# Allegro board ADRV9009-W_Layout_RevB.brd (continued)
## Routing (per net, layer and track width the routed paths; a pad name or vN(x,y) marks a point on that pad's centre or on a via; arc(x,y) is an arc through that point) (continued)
VDD1P3_DIG: length 105.7
  TOP w0.203: P904.1 64.36,10.34 R716.1
  TOP w0.254: v1(37.24,35.68) U101.L9 v1(37.24,34.88) U101.L8 v1(37.24,34.08)
  TOP w0.508: v2(70.65,6.97) v2(69.76,6.97) v2(68.87,6.97) v2(67.98,6.97) v2(67.98,6.21) v2(68.87,6.21) v2(69.76,6.21) v2(70.65,6.21) 71.64,5.22 78.97,5.22 80.14,6.39 R923.2
  TOP w1.27: P904.1 68.02,9.57 C951.1
  L5_SIG w0.508: 65.12,8.49 P904.1 ; P904.1 64.04,9.57 ; P904.1 65.12,10.65 ; P904.1 66.2,9.57
  L5_SIG w1.905: 63.57,9.51 62.86,10.22 55.54,10.22 54.11,11.65 54.11,19.71 v2(52.42,21.4) v2(52.42,22.31) v2(53.47,22.31)
  L8_SIG w0.508: 65.12,8.49 P904.1 ; P904.1 66.2,9.57 ; P904.1 65.12,10.65 ; P904.1 64.04,9.57
  L12_PWR w0.635: v1(37.24,34.88) v1(37.24,35.68)
  L12_PWR w1.016: v1(37.24,34.88) v1(37.24,34.08) 38.25,33.07 40.27,33.07
  L12_PWR w1.27: 48.9,27.61 48.9,29.51 46.23,32.18 41.16,32.18 40.27,33.07
  L12_PWR w1.905: 52.66,22.31 v2(52.42,22.31) v2(52.42,21.4) 53.46,21.4 v2(53.47,21.42) v2(53.47,22.31) 52.66,22.31 ; 52.66,22.31 50.17,24.8 50.17,26.34 48.9,27.61
  BOTTOM w0.305: C643.1 37.1,35.54 v1(37.24,35.68) v1(37.24,34.88) 37.24,34.46 ; 37.24,34.46 v1(37.24,34.08) ; 37.24,34.46 C642.1
  BOTTOM w0.508: P904.1 65.12,10.65 ; P904.1 66.2,9.57 ; P904.1 65.12,8.49 ; P904.1 64.04,9.57
  BOTTOM w0.762: C640.1 64.99,9.44 P904.1
VDD_IF_LDO: length 2.9
  TOP w0.254: 58.1,3.62 58.1,2.46 57.63,1.99 U902.5
  TOP w0.305: U902.7 56.66,3.36
VDD_INTERFACE: length 233.6
  TOP w0.203: R102.1 92.59,45.57 94.19,45.57 v2(94.81,44.94) ; C425.1 100.09,39.42 v2(100.09,39.42) ; v2(117.49,47.87) 117.21,48.14 U402.8
  TOP w0.254: U101.M12 v1(38.04,38.08)
  TOP w0.305: U404.4 120.01,22.36 120.51,21.87 120.51,21.54 120.98,21.06 U404.1 122.11,21.06 v2(122.3,20.87) ; v1(137.83,40.26) 137.92,40.34 R833.1 R832.1 ; U403.1 118.84,48.52 118.19,47.87 v2(117.49,47.87) ; R104.1 93.34,36.75 98.32,36.75 100.09,38.52 v2(100.09,39.42) 100.09,39.99 R108.1 ; 51.03,3.61 51.35,3.29 U902.2 ; v2(122.74,53.6) U403.8 ; R106.1 v2(94.81,44.94) ; R718.1 55.25,13.39 v2(56.78,11.86) ; U902.1 51.41,3.94 51.01,4.35 ; R939.2 50.3,3.95
  TOP w0.394: R111.1 132.75,12.32 v1(132.75,12.32) ; P701.1 v2(60.2,66.02)
  TOP w0.508: 46.98,1.55 P907.1 ; P907.1 48.06,2.63 ; P907.1 45.9,2.63 ; P907.1 46.98,3.71
  TOP w0.762: R938.2 131.45,9.75 v2(131.48,9.78)
  L3_PWR w0.508: v2(94.81,44.94) 95.64,45.76 96.52,45.76 97.05,45.23 97.05,44.94 99.47,42.52 99.83,42.52 100.21,42.15 100.21,41.62 100.09,41.5 v2(100.09,39.42)
  L3_PWR w0.635: v2(77.1,18.72) v2(77.86,18.72) 77.87,18.71 v2(78.75,18.71) 80.03,17.42 85.37,17.42 85.83,16.97 93.51,16.97 95.23,15.26 118.91,15.26 119.83,16.17 122.94,16.17 ; 122.94,16.17 122.94,20.23 v2(122.3,20.87) ; 122.94,16.17 124.59,16.17 127.19,13.57 131.5,13.57 v1(132.75,12.32) 132.75,11.05 v2(131.48,9.78)
  L12_PWR w0.203: 56.78,9.95 v2(56.78,11.86)
  L12_PWR w0.508: 45.9,2.63 P907.1 ; P907.1 46.98,3.71 ; P907.1 48.06,2.63 ; P907.1 46.98,1.55 ; 125.36,40.18 125.36,47.16 123.83,48.69 123.83,52.5 v2(122.74,53.6) ; 115.2,40.43 115.2,46.78 116.28,47.87 v2(117.49,47.87)
  L12_PWR w0.762: 78.5,45 78.5,45.89 76.97,47.42 72.65,47.42 71.38,48.69 71.38,52.36 68.2,55.54 66.93,55.54 66.04,56.43 66.04,59.35 64.26,61.13 64.26,61.95 v2(60.2,66.02) ; v1(38.04,38.08) 41.47,38.08 43.63,40.24 45.53,40.24 49.15,43.85 75.2,43.85 76.08,42.97
  BOTTOM w0.305: v1(38.04,38.08) 38.57,38.61 R110.1
  BOTTOM w0.394: v2(121.54,26.84) 123.19,25.19 123.19,22.65 122.3,21.76 v2(122.3,20.87) 122.07,20.63 C421.2 ; v2(122.74,53.6) 122.81,53.53 C423.2 ; P801.J39 v1(132.75,12.32) ; P801.K40 v2(131.48,9.78)
  BOTTOM w0.762: 46.45,3.16 C934.2 ; 46.45,3.16 46.47,3.14 ; 46.45,3.16 46.45,3.14 46.47,3.14 ; 46.47,3.14 P907.1
VDDA1P3_ANLG: length 67.3
  TOP w0.305: R726.1 v2(44.45,16.41)
  TOP w0.394: R916.2 83.03,20.04
  TOP w0.508: P903.1 77.6,15.46 82.18,20.04 83.03,20.04 ; P903.1 65.06,16.54 ; P903.1 65.06,14.38 ; P903.1 63.98,15.46 ; TP601.1 58.8,15.79 ; TP601.1 57.79,14.77 ; TP601.1 59.82,14.77 ; TP601.1 58.8,13.76
  TOP w0.762: C602.1 64.35,16.17 P903.1 65.23,15.29 68.14,15.29 C950.1
  L8_SIG w0.508: 63.98,15.46 P903.1 ; P903.1 66.14,15.46 ; P903.1 65.06,16.54 ; P903.1 65.06,14.38 ; TP601.1 58.8,15.79 ; TP601.1 57.79,14.77 ; TP601.1 59.82,14.77 ; TP601.1 58.8,13.76
  BOTTOM w0.394: R604.1 28.7,14.02 v6(28.71,14.01) ; R605.1 v2(45.85,18.33)
  BOTTOM w0.508: P903.1 66.14,15.46 ; P903.1 65.06,14.38 ; P903.1 65.06,16.54 ; P903.1 63.98,15.46 ; 58.8,13.76 TP601.1 ; TP601.1 59.82,14.77 ; TP601.1 57.79,14.77 ; TP601.1 58.8,15.79 ; v2(7.5,29.5) 7.5,30.39 R607.1 ; R609.1 v2(7.24,19.6) ; v2(41.53,15.15) v2(41.53,15.91) R601.1
  BOTTOM w0.762: 21.59,57.44 v2(21.6,57.44) 21.6,57.44 21.59,57.44 ; 21.59,57.44 20.84,57.44 R610.1 ; 60.07,17.95 59.73,17.6 59.73,16.97 ; 6.99,48.93 R608.1 ; R606.1 22.23,16.49
  BOTTOM w1.016: 8.38,48.93 8.38,48.94 v8(8.32,48.94) ; 8.38,48.93 6.99,48.93 ; 8.38,48.93 v8(9.65,48.93) ; v8(19.64,61.71) 19.59,61.66 19.59,61.66 ; 19.59,61.66 v8(18.69,60.76) ; 19.59,61.66 E602.1
  BOTTOM w1.143: 22.23,16.49 22.25,16.48 22.25,15.62 22.23,15.61 v2(22.23,15.53)
  vias: v2(49.66,18.33) v2(50.33,18.33) v2(61.35,15.03) v2(61.35,14.27) v2(62.24,15.03) v2(62.24,14.27) v2(63.13,15.03) v2(63.13,14.27)
VDDA1P3_AUX_SYNTH: length 32.2
  TOP w0.254: U101.G8 v5(34.04,34.88)
  L12_PWR w0.279: v5(34.04,34.88) 33.64,35.27 33.64,35.8 33.63,35.82 33.63,35.84 33.4,36.07 33.38,36.07 33.36,36.08 33.07,36.08 32.84,36.31 32.84,36.64 32.61,36.87 30.99,36.87 29.85,38.01 29.85,38.9 29.47,39.28 29.4,39.28 29.4,39.28 29.07,39.28 28.84,39.51 28.84,39.79 28.83,39.8 28.83,39.84 28.39,40.28 v6(28.08,40.28)
  L12_PWR w0.508: v6(28.08,40.28) 22.35,53.76 TP612.1
  BOTTOM w0.305: C633.1 28.07,40.29
  BOTTOM w0.508: 27.94,40.87 27.94,40.42 v6(28.08,40.28) ; 27.94,40.87 28,40.81 C633.1 ; 27.94,40.87 C631.1
  BOTTOM w0.762: 20.65,55.18 20.65,54.85 TP612.1 ; 20.65,55.18 20.65,56.12 20.7,56.17 20.7,56.19 ; 20.65,55.18 20.69,56.17 20.7,56.18 20.7,56.19 ; 20.7,56.19 R610.2
VDDA1P3_AUX_VCO_LDO: length 28.3
  TOP w0.254: v5(30.04,35.68) U101.C10
  L12_PWR w0.508: v6(27.19,33.83) 26.81,33.83 25.82,32.84 25.1,32.84 22.53,30.27 v6(19.24,30.27)
  BOTTOM w0.203: 30.06,35.7 v5(30.04,35.68) ; 13.97,30.39 13.98,30.41 C623.1 ; C622.1 29.5,35.7
  BOTTOM w0.394: 30.06,35.7 28.27,35.7 27.64,35.07 27.64,34.28 v6(27.19,33.83)
  BOTTOM w0.508: v6(19.24,30.27) 19.12,30.39 11.33,30.39 ; 8.64,30.9 8.64,30.41 R607.2 8.63,31.97 TP609.1 8.64,30.9 ; 8.64,30.9 9.65,30.9 10.16,30.39 11.33,30.39 ; 11.33,30.39 C621.1
VDDA1P3_BB: length 21.1
  TOP w0.254: v1(31.64,31.68) U101.E5
  BOTTOM w0.203: C604.1 31.5,31.82 v1(31.64,31.68)
  BOTTOM w0.508: v1(31.64,31.68) 31.25,31.29 C605.1 31.38,30.9 31.94,30.33 31.94,29.44 32.7,28.68 32.7,28.25 33.78,27.18 36.36,27.18 37.15,26.39 37.34,26.39 37.46,26.28 37.84,26.28 38.69,25.42 38.69,25.28 39.11,24.86 39.25,24.86 39.81,24.3 39.87,24.3 40.62,23.54 40.62,22.66 TP603.1 41.4,19.76 C603.1 41.4,19.69 41.4,18.06 R601.2
VDDA1P3_CLOCK_SYNTH: length 21.2
  TOP w0.254: v5(34.04,31.68) U101.G5
  L12_PWR w0.394: TP607.1 45.85,22.56 43.86,24.55 42.67,24.55 41,26.23 39.13,26.23 38.83,25.93 37.87,25.93 36.89,26.91 36.89,29.46 36.21,30.14 35.69,30.14 34.15,31.68 v5(34.04,31.68)
  BOTTOM w0.394: R605.2 TP607.1
  BOTTOM w0.508: C617.1 33.98,31.62 v5(34.04,31.68) 33.97,31.74 C616.1
VDDA1P3_CLOCK_VCO_LDO: length 17.2
  TOP w0.254: v1(38.84,28.48) U101.N1
  BOTTOM w0.203: v1(38.84,28.48) 38.67,28.65 C611.1
  BOTTOM w0.508: R603.2 50.04,20.49
  BOTTOM w0.635: C610.1 40.8,27.82 40.25,28.37 C612.1 38.94,28.37 v1(38.84,28.48)
  BOTTOM w1.016: C610.1 42.26,27.82 42.42,27.98 45.21,27.98 47.5,25.69 47.5,24.42 TP605.1 50.04,20.49
VDDA1P3_DES: length 36.5
  TOP w0.254: v1(38.84,35.68) U101.N9 ; v1(39.64,34.88) U101.P9 v1(39.64,35.68)
  BOTTOM w0.203: C638.1 41.02,35.35
  BOTTOM w0.394: v1(38.84,35.68) v1(39.64,35.68) 39.64,35.35 v1(39.64,34.88)
  BOTTOM w0.508: 39.64,35.35 39.71,35.43 39.8,35.35 41.79,35.35 41.87,35.43 48.95,35.43 52.71,31.67 55,31.67 59.73,26.94 59.73,25.23 ; 60.07,21.37 60.07,22.65 59.98,22.73 ; 60.07,19.22 R611.2
  BOTTOM w0.762: 60.07,19.22 TP614.1 60.07,21.37 59.98,21.46 C637.1 59.98,24.97 59.73,25.23
VDDA1P3_RF_LO: length 16.4
  TOP w0.254: v1(30.04,34.08) U101.C8
  L12_PWR w0.635: 28.82,35.46 29.37,34.7 29.99,34.08 v1(30.04,34.08)
  L12_PWR w0.762: 28.82,35.46 25.75,36.46 21.96,38.27 v6(17.27,38.27) v6(17.27,38.98) v6(17.27,39.69)
  BOTTOM w0.508: C627.1 29.97,34.01 v1(30.04,34.08)
VDDA1P3_RF_SYNTH: length 35.5
  TOP w0.254: v5(34.04,34.08) U101.G7
  L12_PWR w0.203: v7(25.53,60.49) v7(25.02,60.49)
  L12_PWR w0.279: v7(25.53,60.49) 25.53,58.46 29.36,54.63 29.36,50.99 28.95,50.58 28.95,45.24 29.09,45.11 29.09,43.98 28.74,43.64 28.74,42.53 29.34,41.93 29.34,40.55 30.36,39.54 31.37,39.54 33.13,37.78 33.78,37.78 33.87,37.68 34.22,37.68 35.26,36.65 35.26,34.75 35.01,34.5 34.46,34.5 v5(34.04,34.08)
  BOTTOM w0.203: v7(25.53,60.49) v7(25.02,60.49)
  BOTTOM w0.508: v5(34.04,34.08) 34.04,34.07 C609.1
VDDA1P3_RF_VCO_LDO: length 31.3
  TOP w0.254: v1(30.04,32.48) U101.C6 ; U101.C5 v3(30.04,31.68)
  L3_PWR w0.508: v1(30.04,32.48) v3(30.04,31.68)
  L12_PWR w0.508: v6(19.18,27.63) 22.01,27.63 v6(25.66,31.29)
  BOTTOM w0.305: 15.13,26.37 15.15,26.36 C628.1 ; 29.09,32.61 C629.1 30.03,32.49 v1(30.04,32.48)
  BOTTOM w0.394: 29.09,32.61 C630.1 27.68,32.61 27.56,32.49 26.86,32.49 v6(25.66,31.29)
  BOTTOM w0.508: v6(19.18,27.63) 16.39,27.63 13.78,25.02 13.78,21.44 12.7,20.36 TP611.1 12.19,19.85 11.09,18.75 10.37,18.75 9.53,19.6 R609.2
VDDA1P3_RX_RF: length 8.4
  TOP w0.254: U101.B1 v1(29.24,28.48)
  L12_PWR w0.394: v6(28.71,23.03) 28.1,23.64 28.1,24.2 28.71,24.81 v7(28.71,26.06)
  BOTTOM w0.305: 29.23,28.47 v1(29.24,28.48) 29.5,28.74 C615.1
  BOTTOM w0.394: v7(28.71,26.06) 28.71,26.71 ; 28.71,26.71 28.71,27.52 28.91,27.71 28.91,28.14 29.23,28.47 ; 28.71,26.71 C613.1 ; v6(28.71,23.03) 28.7,23.03 R612.2
  BOTTOM w0.508: C614.1 28.92,27.73 28.91,27.71
VDDA1P3_RX_TX: length 11.2
  TOP w0.254: v1(30.04,30.88) U101.C3
  BOTTOM w0.394: C618.1 24.25,18.68 24.25,18.67 ; v1(30.04,30.88) 30.04,30.2 30.29,29.95 C620.1
  BOTTOM w0.762: R606.2 23.28,17.7
  BOTTOM w1.143: v6(26.93,25.95) TP608.1 26.4,22.79 24.25,18.67 23.28,17.7
VDDA1P3_SER: length 30.1
  TOP w0.254: v1(39.64,34.08) U101.P8 v1(38.84,34.08) U101.N8
  BOTTOM w0.203: C634.1 40.2,33.81 40.2,33.8
  BOTTOM w0.394: 40.2,32.89 40.2,32.86 C635.1
  BOTTOM w0.508: C635.1 40.28,32.81 ; 40.28,32.81 40.92,32.17 46.23,32.17 48.64,29.76 50.69,29.76 51.36,29.09 53.9,29.09 56.52,26.47 56.52,23.11 56.52,23.1 TP613.1 ; 40.28,32.81 40.2,32.89 40.2,33.8 39.93,34.08 v1(39.64,34.08) v1(38.84,34.08)
  BOTTOM w1.016: E611.2 TP613.1
VDDA1P8_BB: length 67.4
  TOP w0.254: v5(32.44,30.88) U101.E4
  TOP w0.394: R722.1 v2(49.47,17.18)
  L5_SIG w0.114: v2(49.47,17.18) 49.47,16.49 43.69,10.71 41.02,10.71 40.64,11.09 34.67,11.09 33.91,10.33 31.63,10.33 31.37,10.58 29.59,10.58 27.82,8.8 26.55,8.8 TP903.1
  L10_SIG w0.279: 30.94,28.8 31.24,29.1 31.24,30.24 31.49,30.48 32.04,30.48 v5(32.44,30.88)
  L10_SIG w0.305: 30.94,28.8 30.5,28.8
  L10_SIG w0.394: 30.5,28.8 29.83,28.12 29.83,27.62
  L10_SIG w0.508: 25.02,8.04 25.02,15.28 26.86,17.12 26.86,18.52 28.44,20.1 28.44,23.29 27.94,23.79 27.94,25.73 29.83,27.62
  L10_SIG w0.762: TP903.1 25.02,7.28 25.02,8.04
  BOTTOM w0.305: C944.1 32.51,30.95 v5(32.44,30.88) ; 25.61,5.75 R942.2
  BOTTOM w0.508: v5(32.44,30.88) 32.58,30.73 C945.1
  BOTTOM w1.016: C942.1 24.26,8.55 TP903.1 24.35,6.43 ; 25.61,5.75 25.02,5.75 24.35,6.43 ; 24.35,6.43 C943.1
VDDA1P8_TX: length 61.3
  TOP w0.203: U101.E12 v3(31.64,38.08)
  TOP w0.279: C947.1 v4(26.48,41.06)
  TOP w0.305: C948.1 26.3,40.88 v4(26.48,41.06)
  TOP w0.394: v4(47.39,17.17) R724.1
  TOP w0.508: v2(32.17,24.13) 32.18,24.14 C316.1 32.18,25.43 L316.1 ; TP901.1 100.21,4.74 ; TP901.1 99.19,3.72 ; TP901.1 100.21,2.71 ; TP901.1 101.22,3.72 ; L315.2 37.53,25.43 C315.1 37.53,24.14 v2(37.54,24.13) ; v2(37.5,44.02) 37.49,44.01 C308.1 37.49,42.72 L308.1 ; v2(32.13,44.02) 32.15,44.01 C307.1 32.15,42.72 L307.2
  L3_PWR w0.203: 30.68,39.26 30.67,39.25 30.45,39.25 30.45,39.06 30.47,39.04 30.46,39.03 30.46,38.72 30.72,38.46 31,38.46 31.38,38.08 v3(31.64,38.08) 31.64,38.34 31.26,38.72 31.26,39 31,39.26 30.68,39.26
  L3_PWR w0.305: v2(37.5,44.02) 37.21,43.73 32.43,43.73 v2(32.13,44.02)
  L3_PWR w0.394: v4(47.39,17.17) 46.99,16.78 46.99,16.42 ; v2(32.17,24.13) 32.59,24.55 37.12,24.55 v2(37.54,24.13)
  L3_PWR w0.508: TP901.1 101.22,3.72 ; TP901.1 100.21,2.71 ; TP901.1 100.21,4.74 ; TP901.1 99.19,3.72 ; v4(26.48,41.06) 28.64,41.06 30.45,39.25
  L3_PWR w0.762: 34.84,43.73 34.84,46.94 36.32,48.42 36.42,48.42 36.91,48.91 36.91,49.61 36.42,50.1 36.37,50.1 34.62,51.85 34.14,51.85 33.35,52.64 33.35,53.43 31.53,55.25 31.41,55.25 31.37,55.28 ; 38.33,19.51 38.07,19.78 37.67,19.78 34.81,22.64 34.81,24.55
  vias: v2(101.6,4.74) v2(101.6,2.71) v2(101.86,3.72)
VDDA_1P8: length 113.1
  TOP w0.508: 105.48,4.74 P906.1 ; P906.1 106.56,5.82 ; P906.1 107.64,4.74 ; P906.1 106.56,3.66 ; v2(104.9,5.58) v2(104.14,5.58) v2(103.38,5.58) 102.34,6.62 R931.2
  BOTTOM w0.305: 27.05,5.75 R942.1 ; C940.2 105.54,3.72 P906.1 107.7,3.6 C941.2
  BOTTOM w0.508: P906.1 106.56,5.82 ; P906.1 107.64,4.74 ; P906.1 106.56,3.66 ; P906.1 105.48,4.74
  BOTTOM w1.016: 27.05,5.75 27.94,5.75 28.7,6.52 28.7,11.09 30.23,12.61 34.67,12.61 38.48,8.8 39.88,8.8 42.42,6.26 54.23,6.26 58.04,2.45 59.82,2.45 61.09,1.18 102.49,1.18 104.14,2.83
VDDA_3P3: length 141.4
  TOP w0.254: U101.C12 v3(30.04,38.08)
  TOP w0.394: R720.1 v4(51.56,17.18) ; v1(133.42,62.28) R848.1
  TOP w0.508: R927.2 98.73,20.17 99.61,19.29 v2(101.51,19.29) v2(102.27,19.29) v2(103.04,19.29) 103.04,17.69 R935.1
  L3_PWR w0.203: 31,36.89 31.01,36.9 31.02,36.89 31.21,36.89 31.21,37.11 31.22,37.12 31.22,37.43 30.96,37.69 30.67,37.69 30.29,38.08 v3(30.04,38.08) 30.04,37.82 30.42,37.44 30.42,37.16 30.68,36.89 31,36.89
  L3_PWR w0.508: P905.1 104.45,21.42 ; P905.1 102.29,21.42 ; P905.1 103.37,20.34 ; P905.1 103.37,22.5 ; v2(41.53,60.62) 43.44,58.71 45.72,58.71 ; 45.72,58.71 47.75,58.71 49.15,57.32 51.82,57.32 v2(52.2,57.7) ; 45.72,58.71 45.72,59.86 44.33,61.25 v2(44.33,62.14) ; 45.72,58.71 45.72,56.3 ; 31.21,36.89 31.36,36.74 31.88,36.74 32.51,37.38 32.51,38.14 34.04,39.66 35.71,39.66
  L10_SIG w0.203: 59.06,10.71 57.02,12.75 56,12.75 v4(51.56,17.18)
  L12_PWR w0.394: v2(101.51,19.29) v2(102.27,19.29) v2(103.04,19.29) 106.76,19.29 111.28,23.82 114.46,23.82 115.07,24.43 120.53,24.43 122.27,22.69 129.57,22.69 133.84,26.96 134.27,26.96 134.63,27.31 134.63,27.75 136.31,29.43 138.36,29.43 140.99,32.06 140.99,53.25 139.76,54.48 139.76,57.39 134.87,62.28 v1(133.42,62.28)
  BOTTOM w0.305: R120.1 52.39,57.89 v2(52.2,57.7) ; C135.1 v2(44.33,62.14) ; R119.1 v2(41.53,60.62)
  BOTTOM w0.508: 102.29,21.42 P905.1 ; P905.1 103.37,20.34 ; P905.1 103.37,22.5 ; P905.1 104.45,21.42 ; 44.33,61.32 v2(44.33,62.14)
  vias: v2(57.41,8.68) v2(58.43,8.68) v2(58.47,7.41) v2(58.94,8.05) v2(59.45,8.68) v2(59.45,7.41)
1P3_BUCK_OUT: length 25.4
  L8_SIG w0.394: v2(77.64,6.69) v2(76.87,6.69) v2(76.11,6.69) 75.41,7.4 75.41,18.42 77.23,20.24 84.4,20.24 v2(85.18,21.02)
  BOTTOM w0.394: R905.1 85.59,20.61 v2(85.18,21.02)
3P3V_CLK1: length 38.3
  TOP w0.203: U404.6 119.82,20.88 v2(119.82,20.13) ; C440.2 107.12,66.77 v2(107.63,66.77)
  TOP w0.305: C424.2 117.74,55.17 v2(118.11,55.54) 118.53,55.54 118.84,55.23 U403.14
  TOP w0.394: v2(93.44,59.63) 92.84,59.03 C431.2 ; C436.2 90.27,64.8 v2(90.54,65.06) ; C428.2 v2(93.54,54.83) ; C443.2 85.93,62.84 v2(85.14,63.63) ; C438.2 87.38,64.86 87.38,64.9 v2(87.54,65.06) ; C418.1 85.47,60.3 v2(85.14,60.63) ; v2(86.04,65.06) 86.31,64.8 C439.2 ; C426.1 86.11,57.39 v2(86.11,56.73) ; C442.2 85.71,61.57 v2(85.14,62.14) ; C435.2 91.77,64.8 v2(92.04,65.06) ; v2(89.04,65.06) 88.77,64.8 C437.2 ; C433.2 92.97,62.63 v2(93.45,62.63) ; C434.2 93.41,67.17 v2(93.41,66.78) ; C444.2 v2(83.24,65.13) ; v2(83.2,57.05) 83.31,57.16 C441.2 ; C432.2 92.76,60.47 v2(93.42,61.13) ; v2(93.44,58.13) 93.07,57.76 C430.2 ; v2(95.34,56.63) C429.2 ; v2(88.87,56.77) 88.87,57.43 C427.2
  BOTTOM w0.203: 94.24,56.63 U401.72 ; U405.5 v2(107.63,66.77) ; U401.48 v2(90.54,65.06) ; U401.16 86.04,56.73 v2(86.11,56.73) ; 92.04,65.07 U401.51 ; 89.04,55.93 U401.10 ; U401.39 v2(86.04,65.06) ; U401.69 v2(93.44,58.13) ; U401.1 v2(93.54,54.83) ; U401.66 v2(93.44,59.63)
  BOTTOM w0.254: v2(92.04,65.06) 92.04,65.07 ; U401.42 v2(87.54,65.06) ; U401.60 v2(93.45,62.63) ; U401.33 v2(85.14,63.63) ; v2(83.2,57.05) 83.66,57.05 83.72,57.11 83.8,57.11 83.82,57.13 U401.20 ; U401.63 93.42,61.13 93.42,61.13 93.42,61.13 v2(93.42,61.13) ; U401.30 84.98,62.13 85.03,62.08 85.03,62.14 v2(85.14,62.14) ; U401.36 v2(83.24,65.13) ; U401.45 v2(89.04,65.06) ; v2(95.34,56.63) 94.24,56.63 ; v2(88.87,56.77) 88.87,56.85 88.84,56.85 88.84,56.75 89.04,56.54 89.04,55.93 ; v2(93.41,66.78) 93.41,66.91 93.54,66.78 U401.54 ; U401.27 v2(85.14,60.63)
  BOTTOM w0.394: v2(83.2,57.05) 82.98,56.83 R440.1 ; C422.2 v2(119.82,20.13)
  vias: v2(109.99,19.03) v2(109.99,18.27) v2(110.88,19.03) v2(110.88,18.27) v2(111.77,19.03) v2(111.77,18.27)
3P3V_VCXO: length 64.1
  BOTTOM w0.305: 127.01,62.27 127.01,62.26 C938.2
  BOTTOM w0.394: Y401.6 Y402.6 v2(111,63.8) C407.2
  BOTTOM w0.508: E906.2 103.91,25.59 107.97,25.59 109.86,27.48 111.13,27.48 114.18,30.53 116.21,30.53 118.75,33.07 120.53,33.07 126.5,39.04 126.97,39.04 130.06,42.13 130.06,59.74 127.53,62.27 v2(126.23,62.27) v2(125.56,62.27) 125.56,61.43 124.82,60.69 124.35,60.21 R408.1
3P3VAUX: length 104.4
  TOP w0.305: 126.61,19.28 125.11,19.28 ; 126.61,19.28 C703.1 ; 126.61,19.28 127.66,19.28 v2(127.68,19.26) ; 125.11,19.28 C704.1 ; 125.11,19.28 123.44,19.28 U702.8 ; R710.2 v2(113.8,16.05) ; R709.2 v2(113.8,17.83) ; U703.10 v2(45.49,9.59) ; U703.17 U703.16 ; R708.2 113.21,20.73 v2(112.97,20.97)
  TOP w0.635: U703.16 50.55,9.59 51.2,8.94 v8(51.2,7.67)
  L10_SIG w0.394: v2(45.49,9.59) 46.4,8.68 50.18,8.68 v8(51.2,7.67)
  L10_SIG w0.762: v8(51.2,7.67) 52.84,7.67 57.03,3.48 59.19,3.48 61.6,1.06 105.66,1.06 105.96,0.76 107.15,0.76 107.45,1.06 110.12,1.06 113.8,4.75 v2(113.8,16.05) v2(113.8,17.83) 113.8,20.13 v2(112.97,20.97)
  BOTTOM w0.394: C702.1 51.19,7.68 v8(51.2,7.67) 50.91,7.67 50.22,8.37 C701.2 ; P801.D32 v1(139.1,21.21)
ADP5054_VREG: length 20.4
  TOP w0.394: R903.2 87.86,8.29 v2(88.25,8.68) 88.95,9.38 90.64,9.38 91.04,8.98 91.04,8.83 v2(91.07,8.8) 91.4,9.13 91.4,16.32 v2(89.62,18.1)
  BOTTOM w0.203: 89.03,17.5 88.75,17.22 U901.44 ; 89.03,17.5 89.25,17.28 U901.45 ; 89.03,17.5 v2(89.62,18.1) 89.7,18.17 C902.2
  BOTTOM w0.254: v2(91.07,8.8) 90.75,9.12 U901.13 ; U901.18 v2(88.25,8.68)
AUX_SYNTH_VTUNE: length 49.1
  TOP w0.203: J101.1 56.39,35.98 P104.6
  TOP w0.254: v3(39.64,28.48) U101.P1
  L5_SIG w0.114: P104.6 55.12,40.11 55.12,42.08 51.31,45.89 45.85,45.89 45.27,45.31 44.68,45.31 44.42,45.57 37.91,45.57 36.98,44.64 36.98,44.21 36.68,43.91 36.25,43.91 34.74,42.39 34.74,39.28 34.5,39.05 34.5,31.54 34.76,31.28 34.91,31.28 35.17,31.02 35.17,30.78 36.34,29.61 36.58,29.61 37.33,28.86 39.25,28.86 v3(39.64,28.48)
AUXADC_0: length 64.3
  TOP w0.254: U101.F3 v3(32.44,30.08)
  L8_SIG w0.114: v3(32.44,30.08) 32.1,30.41 32.1,32.46 32.77,33.14 32.77,33.32 33.15,33.69 33.33,33.69 33.65,34.01 33.65,34.24 33.9,34.49 34.2,34.49 34.5,34.79 34.5,35.06 34.78,35.34 34.98,35.34 35.3,35.66 35.3,36.62 35.5,36.81 35.78,36.81 36.1,37.14 36.1,37.42 36.3,37.61 38.85,37.61 39.24,38 39.24,38.15 39.44,38.35 39.72,38.35 39.8,38.27 40.98,38.27 43.28,40.56 44.74,40.56 48.92,44.74 68.8,44.74 72.35,48.3 79.19,48.3 79.89,49 79.89,50.97 P103.3
  BOTTOM w0.203: C131.1 81.09,52.3 P103.3
AUXADC_1: length 66.8
  TOP w0.254: U101.F4 v3(32.44,31.68)
  L7_SIG w0.114: v3(32.44,31.68) 32.44,32 32.1,32.34 32.1,33.29 31.65,33.74 31.5,33.74 31.24,33.99 31.24,34.95 30.98,35.21 30.79,35.21 30.48,35.52 30.48,38.2 30.83,38.54 30.98,38.54 31.17,38.74 31.17,38.89 31.63,39.34 31.78,39.34 31.97,39.54 31.97,39.69 32.2,39.92 32.3,40.01 32.72,40.01 32.83,40.13 32.83,41.63 36.32,45.12 37.47,45.12 40.77,48.43 46.74,48.43 47.69,47.47 63.63,47.47 64.65,48.49 79.95,48.49 81.16,49.7
  BOTTOM w0.203: 81.16,49.7 81.09,49.63 C132.1
AUXADC_2: length 84.2
  TOP w0.254: v3(32.44,36.48) U101.F11
  L5_SIG w0.114: P103.5 76.27,54.58 76.24,54.58 75.94,54.88 75.94,54.91 74.55,56.3 66.04,56.3 62.42,59.92 39.69,59.92 38.1,58.33 30.23,58.33 28.58,56.68 27.56,56.68 25.91,55.03 25.91,51.14 26.59,50.46 26.59,49.42 25.08,47.92 25.08,45.89 25.88,45.09 25.88,40.16 29.23,36.81 32.1,36.81 v3(32.44,36.48)
  BOTTOM w0.203: P103.5 78.55,52.3 C133.1
AUXADC_3: length 82.2
  TOP w0.203: U101.E11 v3(31.64,37.28)
  L5_SIG w0.114: 78.62,49.7 77.35,50.97 77.35,52.68 76.08,53.95 66.24,53.95 61.03,59.16 39.94,59.16 38.48,57.69 36.23,57.69 35.72,57.19 29.93,57.19 28.82,56.09 27.73,56.09 26.5,54.86 26.5,51.39 27.18,50.71 27.18,49.03 25.78,47.63 25.78,46.18 26.93,45.03 26.93,42.21 27.08,42.05 28.51,40.62 28.51,40.17 28.83,39.85 28.83,39.61 29.15,39.28 29.31,39.28 29.57,39.02 29.57,38.79 29.96,38.41 30.18,38.41 30.5,38.09 30.5,37.94 30.74,37.7 31.22,37.7 v3(31.64,37.28)
  BOTTOM w0.203: 78.62,49.7 78.55,49.63 C134.1
CLK+: length 7.5
  BOTTOM w0.203: R406.1 92.72,50.77 ; 92.72,50.77 93.54,50.77 C403.2 ; 92.72,50.77 92.28,50.77 92.06,50.99 92.06,51.72 92.97,52.62 92.97,55.06 93.04,55.13 U401.2
CLK-: length 8.1
  BOTTOM w0.203: 92.72,50.42 92.13,50.42 91.7,50.85 91.7,51.86 92.61,52.77 92.61,55.06 92.54,55.13 U401.3 ; 92.72,50.42 93.54,50.42 C405.2 ; 92.72,50.42 R406.2
CLK_RESETB: length 109.9
  TOP w0.203: v2(120.18,22.92) 119.33,22.92 119.1,22.68 119.1,22.04 119.43,21.71 U404.5
  L7_SIG w0.114: v2(120.18,22.92) 120.75,22.35 121.29,22.35 121.3,22.35 130.27,22.35 131,23.09 134.02,23.09 134.83,23.9 134.83,23.94 135.44,24.56 135.49,24.56 135.76,24.83 135.76,24.87 136.81,25.92 136.86,25.92 137.1,26.16 137.1,26.21 137.64,26.75 137.69,26.75 138.87,27.94 138.87,28.55 142.25,31.92 142.25,46.91 141.94,47.22 137.82,47.22 137.68,47.07 134.72,47.07 132.09,49.7 127.39,49.7 125.23,51.86 105.79,51.86 105.28,51.35 93.8,51.35 92.59,52.55 86.97,52.55 86.9,52.62 86.87,52.62 83.45,56.03 v2(83.45,56.36)
  BOTTOM w0.203: v2(83.45,56.36) 83.72,56.63 U401.19
  BOTTOM w0.394: R440.2 82.93,55.84 v2(83.45,56.36)
CLK_SYSREF_REQUEST: length 36.4
  TOP w0.203: U403.13 v2(119.49,56.68)
  L7_SIG w0.114: v2(119.49,56.68) 118.05,56.68 117.67,57.06 109.6,57.06 109.22,56.68 100.46,56.68 97.73,59.41 v2(97.73,65.95)
  BOTTOM w0.254: U401.57 95.53,64.13 96.27,64.87 96.65,64.87 v2(97.73,65.95) ; R441.2 97.73,66.59
  BOTTOM w0.394: 97.73,66.59 v2(97.73,65.95)
DIR_CLK+: length 12.7
  L10_SIG w0.091: v2(95.63,52.09) 95.63,50.79 95.3,50.47 91.34,50.47 90.84,49.96 88.51,49.96 88.42,50.06 88.42,51.18 88.65,51.41 v2(89.35,51.41)
  BOTTOM w0.203: v2(89.35,51.41) 89.35,51.28 89.78,50.85 R416.2 ; v2(95.63,52.09) 94.88,52.09 C402.2
DIR_CLK-: length 12.8
  L10_SIG w0.091: v2(87.12,51.41) 87.89,51.41 88.16,51.14 88.16,49.95 88.4,49.71 90.95,49.71 91.45,50.21 95.36,50.21 95.63,49.95 v2(95.63,49.09)
  BOTTOM w0.203: C404.2 94.87,49.08 94.88,49.09 v2(95.63,49.09) ; v2(87.12,51.41) 87.12,51.16 86.76,50.79 R415.2
EPROM_A0: length 115.9
  TOP w0.203: U703.11 47.52,8.19 v2(46.87,7.54)
  TOP w0.305: v2(119.89,18.21) 118.85,19.25 U702.1 116.61,19.25 115.77,20.09 R711.2 R708.1
  L8_SIG w0.114: v2(46.87,7.54) 48.39,9.06 52.34,9.06 57.67,3.73 83.58,3.73 84.65,4.81 94.18,4.81 102.5,13.13 114.31,13.13 119.39,18.21 v2(119.89,18.21)
  L10_SIG w0.114: v2(119.89,18.21) 124.08,14.02 136.53,14.02 137.37,14.85 137.37,15.05 139.72,17.4 v1(141.64,17.4)
  BOTTOM w0.394: P801.C34 v1(141.64,17.4)
EPROM_A1: length 115.8
  TOP w0.203: U703.13 48.52,7.92 v2(48.14,7.54)
  TOP w0.305: R709.1 R712.2 116.11,18.95 116.46,18.6 U702.2 118.64,18.6 v2(118.85,18.39)
  L8_SIG w0.114: v2(48.14,7.54) 49.14,8.54 52.09,8.54 57.61,3.03 95.7,3.03 97.67,4.99 99.19,4.99 105.8,11.6 114.06,11.6 120.46,18.01 120.46,18.41 120.02,18.84 119.26,18.84 118.85,18.43 v2(118.85,18.39)
  L10_SIG w0.114: v1(140.37,16.13) 137.5,13.25 123.98,13.25 v2(118.85,18.39)
  BOTTOM w0.394: P801.D35 v1(140.37,16.13)
EPROM_A2: length 4.1
  TOP w0.305: R710.1 R713.2 115.63,17.17 115.97,17.51 116.07,17.51 116.5,17.95 U702.3
FMC_CLK_RESETB: length 24.7
  TOP w0.305: v1(140.37,28.83) 138.57,27.03 138.57,24.82 135.57,21.82 129.86,21.82 128.97,22.71 123.77,22.71 122.77,21.71 U404.2
  BOTTOM w0.394: v1(140.37,28.83) P801.D26
FMC_SYSREF_REQUEST: length 46.4
  TOP w0.203: U403.2 v2(119.49,50.59)
  L8_SIG w0.114: v2(119.49,50.59) 121.74,48.33 125.84,48.33 126.86,49.35 129.4,49.35 132.77,45.97 139.13,45.97 141.18,43.92 141.18,43.88 142.25,42.81 142.25,36.37 141.16,35.29 141.16,31.4 141.16,31.4 141.16,30.93 141.16,30.93 141.16,27.08 v1(140.37,26.29)
  BOTTOM w0.394: v1(140.37,26.29) P801.D27
FMCA_SCL: length 107
  TOP w0.203: v2(50.05,7.54) 49.52,8.06 U703.15
  TOP w0.305: U702.6 122.19,17.95 v2(121.8,18.33)
  L8_SIG w0.114: v2(121.8,18.33) 120.91,17.45 120.91,17.19 113.54,9.82 113.54,8.93 107.95,3.34 103.63,3.34 102.24,1.94 95.76,1.94 95.37,2.33 57.41,2.33 53.73,6.02 51.57,6.02 v2(50.05,7.54)
  L10_SIG w0.114: v1(141.64,22.48) 141.06,21.89 133.87,21.89 130.69,18.71 122.68,18.71 122.31,18.33 v2(121.8,18.33)
  BOTTOM w0.394: v1(141.64,22.48) P801.C30
FMCA_SDA: length 110.4
  TOP w0.203: U703.14 v2(49.02,7.54)
  TOP w0.305: U702.5 v2(121.82,17.3)
  L8_SIG w0.114: v2(49.02,7.54) 49.02,6.15 53.6,1.57 95,1.57 95.77,0.8 107.44,0.8 114.68,8.04 114.68,10.07 121.82,17.21 v2(121.82,17.3)
  L10_SIG w0.114: v1(141.64,21.21) 141.64,21.16 137.3,16.81 127.52,16.81 126.88,16.18 125.1,16.18 123.98,17.3 v2(121.82,17.3)
  BOTTOM w0.394: v1(141.64,21.21) P801.C31
FMCA_VADJ: length 13.2
  TOP w0.762: 131.44,6.74 129.45,6.74 TP814.1 ; 131.44,6.74 131.45,6.73 C932.1 ; 131.44,6.74 R938.1
  L12_PWR w0.508: 128.3,6.87 TP814.1 ; TP814.1 127.28,7.89 ; TP814.1 129.31,7.89 ; TP814.1 128.3,8.91
  BOTTOM w0.394: P801.E39 v1(139.1,11.05) ; P801.H40 v1(134.02,11.05) ; P801.G39 v1(136.56,11.05) ; P801.F40 v1(137.83,9.78)
FMCA_VCC_3P3V: length 7.7
  L12_PWR w0.508: 127.36,11.19 TP818.1 ; TP818.1 128.37,10.17 ; TP818.1 129.39,11.19 ; TP818.1 128.37,12.21
  BOTTOM w0.394: P801.D36 v1(140.37,14.86) ; P801.D40 v1(140.37,9.78) ; P801.D38 v1(140.37,12.32) ; P801.C39 v1(141.64,11.05)
FMCA_VCC_12P0V: length 5.9
  TOP w0.508: 121.29,12.87 TP819.1 ; TP819.1 120.28,13.89 ; TP819.1 122.31,13.89 ; TP819.1 121.29,14.91
  BOTTOM w0.394: P801.C35 v1(141.64,16.13) ; P801.C37 v1(141.64,13.59)
FPGA_REF_CLK+: length 49
  TOP w0.203: C803.1 141.01,56.26 140.5,56.77 v1(140.37,56.77)
  L7_SIG w0.091: v2(108.05,65.17) 108.33,64.89 109.45,64.89 110.26,65.7 126.22,65.7 127.36,64.56 132.84,64.56 139.99,57.41 139.99,57.03 140.25,56.77 v1(140.37,56.77)
  BOTTOM w0.203: v2(108.05,65.17) 107.82,64.94 106.43,64.94 102.03,60.53 99.72,60.53 99.59,60.54 99.25,60.88 98.85,60.88 R420.2
FPGA_REF_CLK-: length 49
  TOP w0.203: v1(139.1,56.77) 138.78,56.77 138.5,56.49 C804.1
  L7_SIG w0.091: v2(108.05,64.36) 108.33,64.63 109.55,64.63 110.37,65.44 126.11,65.44 127.26,64.3 132.74,64.3 139.74,57.3 139.74,56.86 139.65,56.77 v1(139.1,56.77)
  BOTTOM w0.203: R419.2 99.25,59.85 99.58,60.18 99.72,60.18 102.17,60.18 106.58,64.58 107.82,64.58 v2(108.05,64.36)
FPGA_SYSREF+: length 44.5
  TOP w0.203: v1(135.29,55.5) 134.86,55.07 134.86,54.66 135.13,54.66 135.13,54.25 134.86,54.25 134.86,53.01 135.06,52.81 R818.1
  L7_SIG w0.091: v2(99.68,63.79) 99.96,63.51 101.12,63.51 103.25,61.38 129.8,61.38 134.81,56.36 134.81,55.73 135.04,55.5 v1(135.29,55.5)
  BOTTOM w0.203: v2(99.68,63.79) 99.45,63.56 99.15,63.56 R424.2
FPGA_SYSREF-: length 44.5
  TOP w0.203: R819.1 135.58,51.79 134.51,52.86 134.51,55.02 v1(134.02,55.5)
  L7_SIG w0.091: v2(99.68,62.98) 99.96,63.26 101.01,63.26 103.15,61.13 129.69,61.13 134.56,56.26 134.56,55.73 134.33,55.5 v1(134.02,55.5)
  BOTTOM w0.203: v2(99.68,62.98) 99.45,63.21 99.16,63.21 R425.2
FPGA_SYSREF_OUT+: length 46.5
  TOP w0.203: v1(139.1,51.69) 139.64,51.15 R834.1
  L7_SIG w0.091: v1(139.1,51.69) 138.6,51.18 136.31,51.18 135,52.49 132.21,52.49 127,57.7 122.3,57.7 121.41,58.59 101.01,58.59 v2(100.74,58.85)
  BOTTOM w0.203: v2(100.74,58.85) 100.48,58.6 100.16,58.6 99.13,57.57 98.27,57.57 98.01,57.82 R451.1
FPGA_SYSREF_OUT-: length 46.5
  TOP w0.203: R835.1 139.13,50.39 v1(139.1,50.42)
  L7_SIG w0.091: v2(100.74,58.09) 100.98,58.33 121.31,58.33 122.2,57.44 126.9,57.44 132.1,52.24 134.9,52.24 136.21,50.93 139.1,50.93 139.29,50.74 139.29,50.61 v1(139.1,50.42)
  BOTTOM w0.203: R452.1 98.01,56.87 98.35,57.22 99.28,57.22 100.31,58.24 100.59,58.24 v2(100.74,58.09)
GP_INTERRUPT: length 113.9
  TOP w0.254: U101.J5 v3(35.64,32.48)
  TOP w0.394: R805.1 129.63,47.21 TP804.1
  L7_SIG w0.114: v3(35.64,32.48) 35.97,32.14 37.38,32.14 37.7,32.46 37.7,32.62 37.9,32.81 38.18,32.81 38.37,32.62 38.37,32.46 38.7,32.14 40.14,32.14 40.14,32.14 44.23,32.14 45.74,30.63 51.98,30.63 52.53,30.08 54.93,30.08 55.15,29.85 77.19,29.85 77.88,30.55 77.88,30.58 78.19,30.88 78.22,30.88 82.34,35.01 82.34,39.26 83.25,40.17 84.2,40.17 84.89,40.85 84.89,42.03 86.9,44.05 100.4,44.05 103.76,40.68 123,40.68 127.72,45.4 TP804.1
GPIO_0: length 116.9
  TOP w0.203: v1(132.75,37.72) 132.78,37.7 R808.1
  TOP w0.254: U101.K8 v3(36.44,34.08)
  TOP w0.305: 98.62,40.18 95.2,40.18 P101.4 ; 98.62,40.18 R108.2 ; 98.62,40.18 98.62,39.67 R109.1
  L7_SIG w0.114: P101.4 95.07,37.64 126.81,37.64 126.95,37.5 129.07,37.5 129.34,37.76 132.71,37.76 v1(132.75,37.72)
  L8_SIG w0.097: 39.76,33.68 39.41,33.68
  L8_SIG w0.114: 39.41,33.68 36.83,33.68 v3(36.44,34.08) ; 39.76,33.68 39.78,33.68 40.17,33.29 43.14,33.29 43.44,33 46.99,33 48.58,34.58 49.98,34.58 50.29,34.27 51.06,34.27 51.56,34.77 59.37,34.77 60.01,35.41 75.57,35.41 77.35,37.19 77.35,39.47 77.85,39.98 83.89,39.98 84.97,41.06 84.97,42.01 85.54,42.58 90.74,42.58 91.38,43.22 94.24,43.22 95.13,42.33 95.13,40.11 P101.4
GPIO_1: length 129.8
  TOP w0.203: R809.1 132.78,36.43 v1(132.75,36.45)
  TOP w0.254: U101.J8 v3(35.64,34.88)
  TOP w0.305: P101.3 93.52,41.73 R107.1 R106.2
  L7_SIG w0.114: P101.3 93.86,40.43 92.78,39.35 92.78,39.33 92.75,39.31 92.75,38.1 94.24,36.61 117.63,36.61 117.64,36.62 130.91,36.62 131.09,36.45 v1(132.75,36.45)
  L8_SIG w0.114: v3(35.64,34.88) 35.35,34.88 34.93,34.46 34.75,34.46 34.37,34.09 34.37,33.94 32.9,32.46 32.9,30.74 33.23,30.41 33.38,30.41 33.57,30.22 33.57,30.06 34.03,29.61 34.18,29.61 34.37,29.42 34.37,29.26 34.7,28.94 36.78,28.94 37.6,28.11 40.14,28.11 42.05,26.2 43.45,26.2 45.04,24.61 54.29,24.61 54.49,24.81 58.56,24.81 59.32,25.57 85.86,25.57 90.56,30.27 90.56,30.78 91.77,31.99 91.77,35.54 92.62,36.39 92.62,40.14 P101.3
GPIO_2: length 124.6
  TOP w0.203: v1(135.29,38.99) 135.79,38.49 R822.1
  TOP w0.254: U101.J7 v3(34.84,33.28)
  TOP w0.305: R105.1 91.51,36.62 R104.2
  TOP w0.394: P101.6 91.46,38.71 R105.1
  L7_SIG w0.114: P101.6 92.59,40.11 92.59,41.76 93.41,42.58 97.92,42.58 102.27,38.24 126.21,38.24 126.5,38.53 129.81,38.53 130.21,38.94 130.66,38.94 131.2,38.4 134.71,38.4 v1(135.29,38.99)
  L8_SIG w0.114: v3(34.84,33.28) 34.25,33.28 33.66,32.68 33.66,31.54 34.78,30.41 34.98,30.41 35.75,29.64 36.71,29.64 37.41,28.94 39.95,28.94 41.41,27.48 46.49,27.48 47.77,26.2 53.6,26.2 54.54,27.14 84.89,27.14 88.04,30.3 88.04,30.8 90.99,33.76 90.99,35.98 91.32,36.31 P101.6
GPIO_3: length 124.5
  TOP w0.203: v1(132.75,35.18) 133.36,35.79 134.18,35.79 134.88,36.49 R823.1 ; R102.2 R103.1
  TOP w0.254: U101.K7 v3(36.44,33.28)
  TOP w0.305: P101.5 91.29,41.41 91.29,43.83 R103.1
  L7_SIG w0.114: P101.5 90.21,40.27 90.21,37.53 92.91,34.83 115.72,34.83 116.16,34.39 118.68,34.39 119.26,34.96 132.54,34.96 v1(132.75,35.18)
  L8_SIG w0.114: v3(36.44,33.28) 35.97,32.81 35.97,32.34 35.78,32.14 35.63,32.14 35.3,31.82 35.3,31.42 36.3,30.41 36.58,30.41 36.9,30.09 36.9,29.94 37.2,29.64 40.01,29.64 41.28,28.37 48.26,28.37 48.77,27.87 52.21,27.87 52.33,27.99 62.33,27.99 62.33,27.98 83.07,27.98 83.37,28.29 83.37,28.55 90.05,35.22 90.05,40.11 P101.5
GPIO_3P3_0: length 61.8
  TOP w0.254: v3(29.35,27.93) 29.49,27.93 U101.C1
  L8_SIG w0.114: v3(29.35,27.93) 29.24,27.93 28.85,28.32 28.85,28.83 28.46,29.23 28.46,31.04 28.81,31.38 28.81,34.92 29.23,35.34 29.38,35.34 29.39,35.35 29.4,35.35 29.7,35.66 29.7,35.82 29.9,36.01 30.09,36.01 31.3,37.22 31.3,37.42 31.5,37.61 31.66,37.61 33.54,39.49 33.54,44.01 34.23,44.7 34.23,47.47 35.56,48.8 35.56,49.47 35.86,49.77 36.24,49.77 38.01,51.55 38.01,51.83 39.31,53.13 46.48,53.13 46.87,53.51 48.52,53.51 48.64,53.38 49.98,53.38 50.36,53.76 65.04,53.76 P102.3
  BOTTOM w0.203: P102.3 C121.1
GPIO_3P3_1: length 54.5
  TOP w0.254: U101.D1 31.2,28.84 v3(31.2,28.31)
  L8_SIG w0.114: v3(31.2,28.31) 30.43,29.09 30.43,34.94 30.83,35.34 30.98,35.34 31.3,35.66 31.3,35.82 32.3,36.81 32.46,36.81 33.7,38.05 33.7,38.15 33.7,38.15 33.7,38.22 33.9,38.41 34.05,38.41 34.5,38.86 34.5,43.19 36.25,44.94 36.52,44.94 37.85,46.27 39.88,46.27 42.17,48.55 59.31,48.55 59.63,48.24 65.09,48.24 P102.4
  BOTTOM w0.203: P102.4 C122.1
GPIO_3P3_2: length 57.6
  TOP w0.254: U101.E1 v3(31.64,29.28)
  L8_SIG w0.114: P102.5 65.29,50.97 67.12,50.97 67.76,50.33 67.76,49.19 66.23,47.66 48.45,47.66 48.2,47.92 45.91,47.92 43.5,45.51 38.26,45.51 36.99,44.23 36.99,44.14 35.3,42.45 35.3,37.24 34.96,36.9 34.71,36.9 34.37,36.57 34.37,36.34 34.18,36.14 34.03,36.14 33.66,35.77 33.66,35.62 33.38,35.34 33.14,35.34 32.9,35.09 32.18,35.09 31.25,34.16 31.25,31.52 31.25,31.52 31.25,29.66 v3(31.64,29.28)
GPIO_3P3_3: length 52.1
  TOP w0.254: U101.C2 v3(30.04,29.28)
  L8_SIG w0.114: v3(30.04,29.28) 29.59,29.72 29.59,34.96 29.97,35.34 30.18,35.34 30.37,35.54 30.5,35.66 30.5,35.82 30.7,36.01 30.89,36.01 32.04,37.16 32.04,37.41 34.05,39.42 34.05,43.73 34.8,44.49 34.8,45.51 36.27,46.97 39.24,46.97 40.91,48.64 40.91,49.84 41.75,50.68 48.93,50.68 49.28,51.03 62.69,51.03 P102.6
GPIO_3P3_4: length 70.6
  TOP w0.254: U101.D2 v3(30.84,29.28)
  L7_SIG w0.114: v3(30.84,29.28) 30.43,29.69 30.43,30.24 30.2,30.46 29.9,30.46 29.59,30.77 29.59,31.8 29.28,32.11 28.77,32.11 27.16,33.72 27.16,35.62 26.23,36.55 26.23,40.55 25.85,40.93 25.85,48.11 26.61,48.87 26.61,55.67 29.66,58.71 39.44,58.71 40.07,59.35 42.46,59.35 48.42,53.38 60.34,53.38 P102.7
  BOTTOM w0.203: P102.7 C123.1
GPIO_3P3_5: length 64.2
  TOP w0.254: U101.E2 v3(31.64,30.08)
  L7_SIG w0.114: v3(31.64,30.08) 32.03,30.46 32.03,31.84 31.8,32.06 31.57,32.06 31.17,32.46 31.17,32.62 30.48,33.31 30.48,34.33 30.27,34.54 29.9,34.54 29.57,34.86 29.57,40.06 29.47,40.17 29.47,42.18 29.85,42.56 29.85,43.97 29.02,44.81 29.02,50.65 29.59,51.22 29.59,53.95 30.31,54.67 34.01,54.67 34.31,54.96 34.73,54.96 34.76,54.94 39.14,54.94 40.26,53.82 41.85,53.82 45.66,50.01 47.18,50.01 48.77,48.43 60.52,48.43 61.48,49.39 P102.8
  BOTTOM w0.203: P102.8 C124.1
GPIO_3P3_6: length 62.4
  TOP w0.254: U101.E3 v3(31.64,30.88)
  L7_SIG w0.114: v3(31.64,30.88) 31.3,31.21 30.81,31.21 30.37,31.64 30.37,31.82 30.18,32.01 29.95,32.01 29.57,32.39 29.57,32.62 29.38,32.81 29.21,32.81 28.77,33.24 28.77,35.34 27.52,36.6 27.52,42.63 26.86,43.28 26.86,45.63 27.82,46.59 27.82,52.11 28.64,52.94 28.64,54.14 29.94,55.44 31.04,55.44 31.23,55.64 34.9,55.64 35.5,56.24 42.17,56.24 45.53,52.87 46.42,52.87 48.34,50.95 57.64,50.95 P102.9
  BOTTOM w0.203: P102.9 C125.1
GPIO_3P3_7: length 38.1
  TOP w0.254: v3(31.64,38.88) U101.E13
  L5_SIG w0.114: v3(31.64,38.88) 31.97,38.54 32.98,38.54 34.1,39.66 34.1,43.28 36.06,45.25 36.06,45.97 36.36,46.27 40.52,46.27 41.59,47.34 45.65,47.34 46.14,47.83 47.22,47.83 47.71,47.34 57.84,47.34 58.94,48.43 P102.10
  BOTTOM w0.203: P102.10 C126.1
GPIO_3P3_8: length 55.1
  TOP w0.254: v3(30.84,38.88) U101.D13
  L5_SIG w0.114: v3(30.84,38.88) 31.21,39.25 33.02,39.25 33.53,39.76 33.53,44 33.74,44.21 33.74,44.57 36.13,46.97 40.01,46.97 41.47,48.43 57.1,48.43 57.66,49 57.66,50.98 P102.11
  L10_SIG w0.114: P102.11 54.88,53.76 52.83,53.76 47.69,58.9 v2(47.69,61.32)
  BOTTOM w0.203: U102.1 v2(47.69,61.32) ; P102.11 C127.1
GPIO_3P3_9: length 55.5
  TOP w0.203: P102.12 56.26,49.57 C128.1
  TOP w0.254: v3(30.04,38.88) U101.C13
  L5_SIG w0.114: P102.12 55.18,50.92 55.18,53.19 53.41,54.97 48.96,54.97 46.33,57.6 v2(42.01,57.6) 41.83,57.6 40.28,56.05 35.37,56.05 34.86,55.54 30.16,55.54 28.57,53.94 28.57,52.29 28.2,51.92 28.2,45.63 28.97,44.85 28.97,43.13 28.83,42.99 28.83,42.56 28.97,42.42 28.97,40.42 29.37,40.01 29.38,40.01 29.57,39.82 29.57,39.81 30.04,39.35 v3(30.04,38.88)
  BOTTOM w0.203: v2(42.01,57.6) 43.18,58.78 44.33,58.78
GPIO_3P3_10: length 46.4
  TOP w0.254: U101.D14 v3(30.84,39.68)
  L5_SIG w0.114: P102.13 52.47,53.63 49.61,53.63 49.36,53.38 48.93,53.38 48.36,53.95 47.56,53.95 44.9,56.62 v2(44.33,56.62) 41.59,56.62 39.75,54.78 34.92,54.78 34.73,54.96 34.31,54.96 34.12,54.78 30.39,54.78 29.41,53.8 29.41,50.82 28.89,50.3 28.89,45.82 29.41,45.31 29.41,44.9 29.53,44.78 29.53,43.32 29.85,42.99 29.85,42.56 29.47,42.17 29.47,40.63 30.42,39.68 v3(30.84,39.68)
  BOTTOM w0.203: v2(44.33,56.62) 44.33,57.51 ; P102.13 C129.1
GPIO_3P3_11: length 45.7
  TOP w0.203: P102.14 53.85,49.7 C130.1
  TOP w0.254: U101.E14 v3(31.64,39.68)
  L5_SIG w0.114: v3(31.64,39.68) 31.96,39.68 32.3,40.01 32.43,40.01 32.7,40.28 32.7,46.2 35.56,49.06 35.56,49.47 36.29,50.2 36.71,50.2 37.59,51.09 37.59,51.47 39.37,53.25 41.53,53.25 43.88,55.6 v2(44.83,55.6) 45.09,55.6 47.06,53.63 47.06,52.81 48.45,51.41 50.1,51.41 50.61,50.9 52.66,50.9 P102.14
  BOTTOM w0.203: U102.2 48.01,60.05 46.99,59.03 46.99,57.25 45.34,55.6 v2(44.83,55.6)
GPIO_4: length 113.1
  TOP w0.203: P101.8 88.78,37.02 88.78,37.01 R707.2 ; R812.1 132.78,30.08 v1(132.75,30.1)
  TOP w0.254: U101.K6 v3(36.44,32.48)
  L7_SIG w0.114: v1(132.75,30.1) 130.1,32.75 118.31,32.75 117.69,33.37 113.72,33.37 113.42,33.07 92.32,33.07 88.78,36.61 P101.8
  L8_SIG w0.114: P101.8 88.78,36.09 88.15,35.46 87.62,35.46 83.72,31.56 62.93,31.56 61.22,29.85 55.55,29.85 55.44,29.96 54.18,29.96 53.48,29.26 49.67,29.26 49.36,28.95 41.47,28.95 39.87,30.54 38.98,30.54 37.1,30.54 36.9,30.74 36.9,30.89 36.58,31.21 36.41,31.21 36.2,31.42 36.21,31.43 36.1,31.54 36.1,31.82 36.21,31.92 36.21,31.93 36.44,32.16 v3(36.44,32.48)
GPIO_5: length 63.2
  TOP w0.203: R705.2 89.91,43.67 R813.1
  TOP w0.254: U101.K5 v3(36.44,31.68)
  TOP w0.305: P101.7 88.82,41.42 R705.2
  L8_SIG w0.097: 39.89,31.29 39.51,31.29
  L8_SIG w0.114: 39.89,31.29 40.78,30.4 49.67,30.4 49.92,30.65 53.6,30.65 54.3,31.35 59.88,31.35 61.42,32.88 82.25,32.88 84.46,35.1 85.54,35.1 87.51,37.06 87.51,40.11 P101.7 ; v3(36.44,31.68) 36.76,31.68 37.15,31.29 39.51,31.29
GPIO_6: length 120
  TOP w0.203: R843.1 141.67,33.93 v1(141.65,33.95)
  TOP w0.254: U101.L5 v3(37.24,31.68)
  TOP w0.305: P101.10 86.65,38.44 R706.2
  L7_SIG w0.114: v1(141.65,33.95) 141.11,34.49 141.11,35.06 137.03,39.14 137.03,39.18 135.27,40.93 125.03,40.93 124.03,39.93 123.27,39.93 123.22,39.98 102.94,39.98 99.63,43.28 88.97,43.28 87.51,41.82 87.51,40.11 P101.10
  L8_SIG w0.114: P101.10 86.24,37.77 84.97,36.5 82.81,36.5 82.81,36.49 82.65,36.49 80.16,34.01 80.16,33.89 79.66,33.39 60.4,33.39 59.77,32.75 57.85,32.75 56.96,31.86 55.32,31.86 55.19,31.98 49.85,31.98 49.28,31.42 40.52,31.42 39.89,32.05 37.61,32.05 v3(37.24,31.68)
GPIO_7: length 123.4
  TOP w0.203: v3(137.8,31.35) 138.69,31.35 139.26,31.92 R844.1
  TOP w0.254: U101.L6 v3(37.24,32.48)
  TOP w0.305: R702.2 86.23,43.62 86.23,41.4 P101.9
  L7_SIG w0.114: P101.9 86.24,40.81 84.97,39.54 84.97,37.52 89.54,32.94 89.54,32.3 90.43,31.42 91.07,31.42 91.2,31.28 113.6,31.28 114.49,30.39 117.79,30.39 118.93,29.26 120.72,29.26 121.1,29.64 126.17,29.64 126.88,28.93 130.64,28.93 130.7,28.99 131.31,28.99 132.07,28.23 134.49,28.23 135.65,29.38 136.66,29.38 137.16,29.88 137.16,30.71 v3(137.8,31.35)
  L8_SIG w0.114: P101.9 86.24,40.43 84.97,39.16 84.97,38.27 84.34,37.64 81.03,37.64 78.11,34.72 60.72,34.72 59.38,33.38 49.6,33.38 48.2,31.98 47.25,31.98 47.18,32.05 40.65,32.05 39.76,32.94 38.7,32.94 37.7,32.94 v3(37.24,32.48)
GPIO_8: length 131.5
  TOP w0.203: R827.1 136.18,29.72 v1(136.56,30.1)
  TOP w0.254: U101.L12 v3(37.24,38.08)
  L5_SIG w0.091: v1(136.56,30.1) 136.56,30.8 136.47,30.89 135.86,30.89 135.77,30.8 135.77,29.75 135.96,29.56 138.5,29.56 138.81,29.87 138.81,37.55 136.81,39.54 131.22,39.54 129.95,40.81 124.11,40.81 123.86,41.07 103.13,41.07 101.55,42.65 92.99,42.65 92.41,43.23 85.16,43.23 84.52,42.59 84.52,42.2 84.84,41.89 84.84,40.62 83.7,39.48 P101.12
  L10_SIG w0.091: P101.12 83.7,37.64 82.73,36.67 73.44,36.67 67.41,42.7 56.27,42.7 55.56,43.41 48.83,43.41 48.14,42.71 43.37,42.71 42.74,42.08 38.08,42.08 37.05,41.04 37.05,40.06 37.1,40 37.37,40 37.56,39.81 37.56,38.47 37.42,38.33 37.42,38.26 v3(37.24,38.08)
GPIO_9: length 123
  TOP w0.203: R810.1 134.33,33.6 v1(134.02,33.91)
  TOP w0.254: U101.K12 v3(36.44,38.08)
  L5_SIG w0.091: P101.11 82.55,40.24 82.55,38.44 83.25,37.75 84.16,37.75 84.17,37.76 84.22,37.76 84.89,38.42 84.89,39.41 85.72,40.24 101.58,40.24 102.15,39.66 124.06,39.66 129.27,34.46 131.38,34.46 132.44,33.4 133.93,33.4 134.02,33.49 v1(134.02,33.91)
  L10_SIG w0.091: v3(36.44,38.08) 36.08,38.43 36.08,39.08 35.85,39.31 35.76,39.31 35.66,39.4 35.66,42.39 36.49,43.22 39.35,43.22 40.52,44.39 73.91,44.39 75.72,42.58 79.21,42.58 79.76,42.03 79.76,38.03 80.48,37.31 81.77,37.31 82.55,38.1 82.55,40.24 P101.11
GPIO_10: length 123
  TOP w0.203: R811.1 134.33,32.33 v1(134.02,32.64)
  TOP w0.254: U101.J12 v3(35.64,38.08)
  L5_SIG w0.091: v1(134.02,32.64) 134.02,33.06 133.93,33.15 132.33,33.15 131.28,34.2 129.16,34.2 123.95,39.41 102.05,39.41 101.48,39.98 85.82,39.98 85.14,39.3 85.14,38.32 84.33,37.5 84.28,37.5 84.26,37.49 83.14,37.49 82.3,38.33 82.3,39.89 82.21,39.98 81.25,39.98 81.16,39.89 P101.14
  L10_SIG w0.091: P101.14 81.16,39.16 81.71,39.71 82.21,39.71 82.3,39.62 82.3,38.2 81.66,37.57 80.58,37.57 80.01,38.14 80.01,42.14 79.31,42.84 75.82,42.84 74.01,44.65 40.42,44.65 39.24,43.47 36.39,43.47 35.41,42.5 35.41,39.17 35.31,39.07 35.31,38.4 v3(35.64,38.08)
GPIO_11: length 117.2
  TOP w0.203: R824.1 135.26,35.14 v1(135.29,35.18)
  TOP w0.254: U101.H12 v3(34.84,38.08)
  L5_SIG w0.091: P101.13 80.72,41.39 80.01,40.68 80.01,38.2 81.28,36.93 87.21,36.93 87.74,37.47 115.59,37.47 116.44,36.62 117.92,36.62 118.3,37 122.62,37 126.94,32.68 128.27,32.68 128.56,32.97 130.01,32.97 130.8,32.19 134.21,32.19 134.48,32.45 134.48,32.82 135.1,33.44 135.46,33.44 135.8,33.78 135.8,35.09 135.71,35.18 v1(135.29,35.18)
  L7_SIG w0.091: P101.13 80.52,40.74 80.27,40.74 80.04,40.97 80.04,42.12 79.01,43.16 65.62,43.16 62.74,40.28 45.85,40.28 44.02,38.45 35.21,38.45 35.07,38.31 v3(34.84,38.08)
GPIO_12: length 116.8
  TOP w0.203: v1(136.56,35.18) 136.53,35.14 R825.1
  TOP w0.254: U101.H11 v3(34.84,37.28)
  L5_SIG w0.091: P101.16 79.45,38.85 79.76,38.53 79.76,38.1 81.18,36.68 87.31,36.68 87.85,37.21 115.48,37.21 116.33,36.36 118.03,36.36 118.41,36.74 122.52,36.74 126.83,32.42 128.38,32.42 128.67,32.72 129.91,32.72 130.69,31.93 134.32,31.93 134.73,32.35 134.73,32.71 135.2,33.19 135.57,33.19 136.06,33.67 136.06,35.09 136.15,35.18 v1(136.56,35.18)
  L7_SIG w0.091: v3(34.84,37.28) 35.25,37.69 39.71,37.69 39.92,37.89 39.92,38.06 40.06,38.2 44.13,38.2 45.96,40.02 62.85,40.02 65.72,42.9 78.9,42.9 79.79,42.02 79.79,40.9 78.62,39.73 P101.16
GPIO_13: length 121.4
  TOP w0.203: R831.1 135.32,42.77 v1(135.29,42.8)
  TOP w0.254: U101.J11 v3(35.64,37.28)
  L5_SIG w0.091: v1(135.29,42.8) 135.39,42.9 135.39,43.53 135.75,43.88 135.75,44.26 135.38,44.62 132.5,44.62 131.62,43.73 125.22,43.73 124.71,44.24 116.59,44.24 114.69,42.34 104.66,42.34 102.93,44.06 92.82,44.06 92.14,44.74 78.47,44.74 76.88,43.16 76.31,43.16 75.64,42.49 75.63,42.49 74.98,41.84 74.98,40.61 75.3,40.29 77.52,40.29 P101.15
  L7_SIG w0.091: v3(35.64,37.28) 36.07,36.84 36.54,36.84 36.7,36.69 36.83,36.69 36.91,36.61 36.91,36.34 37.1,36.15 37.34,36.15 37.71,35.78 37.71,35.54 37.9,35.35 38.14,35.35 38.77,34.72 39.26,34.72 39.48,34.5 39.79,34.5 39.99,34.7 42.02,34.7 42.55,35.23 48.97,35.23 49.19,35.45 51.74,35.45 52.28,34.9 73.2,34.9 75.42,37.12 76.33,37.12 77.47,38.26 77.47,40.24 P101.15
GPIO_14: length 121.4
  TOP w0.203: v1(136.56,42.8) 136.46,42.7 R830.1
  TOP w0.254: U101.K11 v3(36.44,37.28)
  L5_SIG w0.091: P101.18 77.16,38.85 77.35,39.03 77.35,39.79 77.1,40.03 75.2,40.03 74.73,40.5 74.73,41.95 75.52,42.74 75.53,42.74 76.2,43.41 76.77,43.41 78.36,45 92.25,45 92.93,44.32 103.04,44.32 104.76,42.59 114.58,42.59 116.49,44.5 124.81,44.5 125.32,43.99 131.52,43.99 132.4,44.87 135.49,44.87 136,44.36 136,43.78 135.64,43.42 135.64,43.09 135.93,42.8 v1(136.56,42.8)
  L7_SIG w0.091: P101.18 76.57,39.33 77.12,39.33 77.22,39.23 77.22,38.37 76.23,37.38 75.31,37.38 73.09,35.16 52.39,35.16 51.84,35.7 49.09,35.7 48.86,35.48 42.45,35.48 41.92,34.95 40.1,34.95 39.79,35.25 39.48,35.25 39.2,34.97 38.88,34.97 38.36,35.49 38.36,35.81 38.17,36 37.85,36 37.56,36.29 37.56,36.61 37.37,36.8 37.08,36.8 36.94,36.94 36.8,36.94 36.47,37.28 v3(36.44,37.28)
GPIO_15: length 131.8
  TOP w0.203: R826.1 135.62,30.42 v1(135.29,30.1)
  TOP w0.254: U101.L11 v3(37.24,37.28)
  L5_SIG w0.091: P101.17 77.28,42.58 84.15,42.58 85.05,43.48 92.51,43.48 93.09,42.9 101.66,42.9 103.24,41.32 123.96,41.32 124.22,41.07 130.06,41.07 131.33,39.8 136.91,39.8 139.06,37.65 139.06,29.76 138.6,29.3 135.86,29.3 135.29,29.87 v1(135.29,30.1)
  L10_SIG w0.091: P101.17 75.64,41.83 75.05,41.83 74.81,41.59 74.81,37.08 74.71,36.99 73.48,36.99 67.51,42.96 56.38,42.96 55.67,43.66 48.73,43.66 48.03,42.97 43.27,42.97 42.63,42.33 37.98,42.33 36.79,41.15 36.79,37.37 36.88,37.28 v3(37.24,37.28)
GPIO_16: length 115.5
  TOP w0.203: v1(141.64,49.15) 141.64,48.84 R817.1
  TOP w0.254: U101.M11 v3(38.04,37.28)
  L5_SIG w0.091: v3(69.67,41.88) 70.04,41.88 73.54,45.38 74.19,45.38 77.37,48.55 87.12,48.55 88.9,50.33 97.16,50.33 102.24,55.41 109.2,55.41 109.84,54.78 123.23,54.78 125.39,52.62 130.18,52.62 132.84,49.95 140.85,49.95 141.1,49.7 141.1,49.32 141.27,49.15 v1(141.64,49.15)
  L7_SIG w0.091: v3(69.67,41.88) 69.67,41.51 65.85,37.7 52.03,37.7 51.59,37.25 48.22,37.25 48.03,37.06 41.09,37.06 40.83,36.8 38.82,36.8 38.35,37.28 v3(38.04,37.28)
GPIO_17: length 115.4
  TOP w0.203: v1(140.37,49.15) 140.37,48.84 R816.1
  TOP w0.254: U101.M10 v3(38.04,36.48)
  L5_SIG w0.091: v3(70.22,41.33) 70.22,41.7 71.15,42.64 73.64,45.12 74.3,45.12 77.47,48.3 87.23,48.3 89.01,50.08 97.26,50.08 102.34,55.16 109.1,55.16 109.73,54.52 123.13,54.52 125.29,52.36 130.07,52.36 132.74,49.7 140.74,49.7 140.85,49.59 140.85,49.38 140.61,49.15 v1(140.37,49.15)
  L7_SIG w0.091: v3(38.04,36.48) 38.38,36.48 38.77,36.09 38.91,36.09 39.16,36.34 39.22,36.34 39.47,36.09 39.75,36.09 39.94,36.28 39.94,36.46 40.02,36.55 40.93,36.55 41.19,36.81 48.14,36.81 48.33,37 51.69,37 52.14,37.44 65.96,37.44 69.85,41.33 v3(70.22,41.33)
GPIO_18: length 34.6
  TOP w0.203: R113.1 58.99,36.42 58.99,35.29 R704.2
  TOP w0.254: U101.J3 v3(34.84,30.88)
  TOP w0.305: R113.1 58.99,38.77 P104.4
  L8_SIG w0.114: v3(34.84,30.88) 34.5,31.21 34.5,31.82 34.83,32.14 34.98,32.14 35.19,32.35 35.19,33.32 36.36,34.49 41.75,34.49 42.67,35.41 48.39,35.41 49.91,36.93 52.07,36.93 52.71,37.57 57.66,37.57 P104.4
  BOTTOM w0.203: R837.1 P104.4
INPUT_VOLTAGE: length 42
  TOP w0.203: DS901.A 121.36,5.44 CR901.C
  TOP w0.305: R714.2 v2(55.9,7.29)
  L7_SIG w0.114: v2(55.9,7.29) 56.41,6.78 60.21,6.78 62.37,4.62 80.18,4.62 v2(84.09,8.52)
  BOTTOM w0.254: 85.26,17.59 85.75,17.1 U901.38 ; U901.36 84.03,15.92 83.53,16.42 ; v2(92.49,13.17) 92.8,13.17 v2(93.15,12.81) ; v2(92.49,13.17) 92.24,13.42 U901.6 ; v2(92.49,13.17) 92.24,12.92 U901.7 ; U901.22 86.25,9.16 v2(85.59,8.5)
  BOTTOM w0.394: R909.1 v2(92.94,18.39)
  vias: v2(83.38,18.28) v2(83.71,16.73) v2(84.24,18.28) v2(84.57,16.73) v2(84.82,8.5) v2(98.77,13.32) v2(98.77,12.43) v2(98.77,11.57) v8(117.74,6.02) v8(117.74,4.3) v8(119.26,6.02) v8(119.26,4.3) v8(123.71,6.02) v8(123.71,4.3) v8(125.23,6.02) v8(125.23,4.3)
JTAG_TDI: length 1.6
  TOP w0.305: R840.2 140.04,22.15 v1(140.37,22.48)
  BOTTOM w0.394: v1(140.37,22.48) P801.D30
JTAG_TDO: length 1.6
  TOP w0.305: R840.1 140.07,21.51 v1(140.37,21.21)
  BOTTOM w0.394: v1(140.37,21.21) P801.D31
LDO_VCO_2P5: length 3.2
  BOTTOM w0.203: C416.1 86.25,54.23
  BOTTOM w0.254: C417.1 86.24,54.22 86.55,54.53 86.55,55.04 86.54,55.05 86.54,55.37 U401.15
LF_EXT_CAP: length 2.9
  BOTTOM w0.203: R439.2 90.11,53.81 C414.2
  BOTTOM w0.254: U401.7 90.54,55.18 90.54,54.29 R439.2
LF_PLL2: length 2.3
  BOTTOM w0.254: C416.2 87.24,53.86 87.25,53.85 87.25,54.61 87.04,54.82 U401.14
ORX1_BAL+: length 3.2
  BOTTOM w0.203: C218.2 22.03,43.29 22.04,43.38 ; 22.04,43.38 22.26,43 arc(22.38,42.65) R220.1 ; 22.04,43.38 21.77,43.85 arc(21.36,44.31) T205.4
ORX1_BAL-: length 3.3
  BOTTOM w0.127: R219.1 23.15,42.73 ; 22.28,43.68 22.38,43.49 C218.1
  BOTTOM w0.203: T205.5 arc(21.88,44.61) 22.07,44.03 22.28,43.68 22.41,43.45 22.51,43.28 22.57,43.17 arc(22.72,42.97) 22.93,42.82 arc(23.03,42.77) 23.15,42.73
ORX1_IN+: length 7.9
  BOTTOM w0.203: C221.2 23.44,40.95 ; 23.44,40.95 23.55,40.72 arc(23.61,40.61) 23.68,40.51 arc(25.7,38.51) 28.43,37.72 arc(28.64,37.71) v5(28.84,37.68) ; 23.44,40.95 23.36,41.1 arc(23.07,41.47) R220.2
ORX1_IN-: length 7.8
  BOTTOM w0.203: 23.75,41.11 23.86,40.89 arc(23.92,40.79) 23.98,40.7 arc(25.88,38.82) 28.44,38.08 arc(28.53,38.08) 28.61,38.1 arc(28.71,38.15) 28.8,38.21 arc(28.86,38.34) v5(28.84,38.48) ; 23.75,41.11 C221.1 ; 23.75,41.11 23.66,41.28 arc(23.5,41.71) R219.2
ORX1_UNBAL: length 2.3
  BOTTOM w0.203: 17.98,49.53 C250.1 ; C217.1 17.61,50.43
  BOTTOM w0.305: R216.2 17.22,51.28
  BOTTOM w0.394: 17.22,51.28 17.61,50.43 17.98,49.53
ORX2_BAL+: length 3.1
  BOTTOM w0.203: 22.54,24.32 22.19,23.82 arc(21.94,23.26) 21.93,22.65 ; 22.54,24.32 C225.2 ; 22.54,24.32 22.76,24.63 arc(23.02,24.89) R227.1
ORX2_BAL-: length 3.1
  BOTTOM w0.203: 22.25,24.53 22.46,24.83 arc(22.61,25.18) R226.1 ; 22.25,24.53 22.16,24.4 21.9,24.02 arc(21.46,23.6) 20.89,23.38 ; 22.25,24.53 C225.1
ORX2_IN+: length 7.6
  BOTTOM w0.203: C228.2 24.12,26.59 ; 24.12,26.59 arc(24.04,26.46) 23.95,26.33 arc(23.81,26.01) 23.74,25.66 arc(23.74,25.6) R227.2 ; 24.12,26.59 arc(25.79,28.49) 27.87,29.94 arc(28.14,30.04) 28.43,30.08 arc(28.52,30.07) 28.61,30.05 arc(28.71,30.01) 28.8,29.94 arc(28.86,29.81) v5(28.84,29.68)
ORX2_IN-: length 7.7
  BOTTOM w0.203: C228.1 23.82,26.79 ; 23.82,26.79 arc(23.74,26.66) 23.65,26.53 arc(23.36,26.23) R226.2 ; 23.82,26.79 arc(25.55,28.76) 27.71,30.25 arc(28.06,30.39) 28.43,30.43 arc(28.64,30.44) v5(28.84,30.48)
